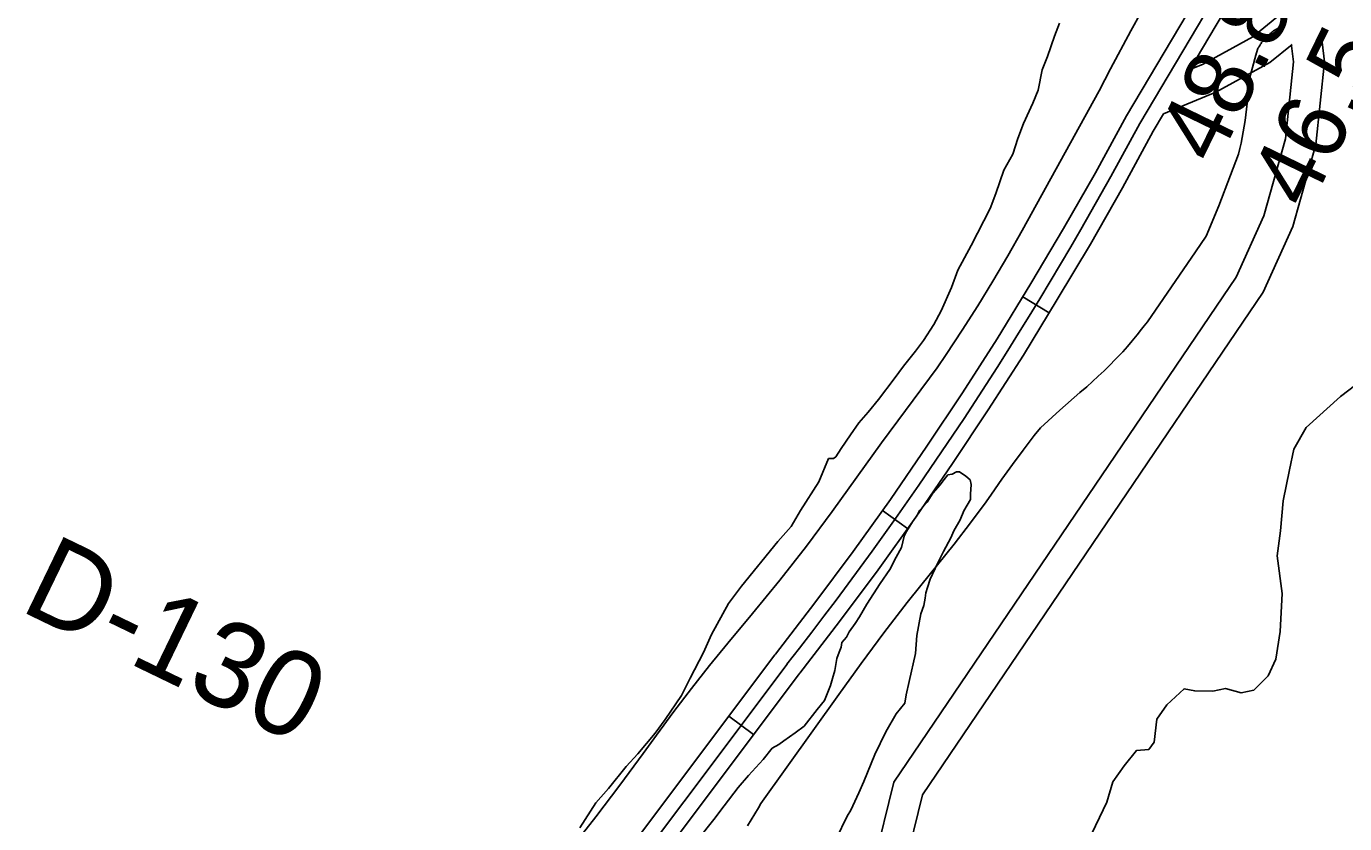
# Model space of a CAD drawing. Extents: x 3180038 to 3217926, y 922069 to 947485.
# Drawn here: x 3187258 to 3188541, y 935984 to 936760 of the extents above; entities that cross this region are included whole.
import ezdxf

# ---------------------------------------------------------------- set-up
doc = ezdxf.new("R2010")
doc.units = 0
for name, color, linetype in [('V-LEVE-TOET', 7, 'Continuous'), ('V-RIVR-EDGE', 7, 'Continuous'), ('V-RIVR-RANG', 7, 'Continuous'), ('V-RIVR-RANG-IDEN', 7, 'Continuous'), ('V-ROAD-CNTR', 7, 'Continuous'), ('V-SITE-VEGE', 7, 'Continuous')]:
    doc.layers.add(name, color=color, linetype=linetype)

msp = doc.modelspace()

# ---------------------------------------------------------------- linework, layer by layer
at = {"layer": 'V-LEVE-TOET'}
for points in [[(3188352.9, 936791.9), (3188332.6, 936755.3), (3188312.8, 936718.4), (3188301.8, 936697.1), (3188301.8, 936697.1), (3188226.8, 936561), (3188226.8, 936561), (3188212.9, 936536.4), (3188198.5, 936512), (3188183.8, 936487.9), (3188168.6, 936464.1), (3188153, 936440.5), (3188144.3, 936427.7), (3188144.3, 936427.7), (3188090.1, 936354.6), (3188042.2, 936287.7), (3188042.2, 936287.7), (3188017, 936254.2), (3187991.1, 936221.1), (3187964.7, 936188.4), (3187940.7, 936159.7), (3187940.7, 936159.7), (3187922.7, 936137.8), (3187905.1, 936115.6), (3187888, 936093.1), (3187871.2, 936070.3), (3187858.3, 936052.3), (3187858.3, 936052.3), (3187835.5, 936021.4), (3187812.2, 935990.8), (3187788.4, 935960.7)], [(3188466.8, 936751.6), (3188467.4, 936752.1), (3188468.1, 936752.7), (3188468.7, 936753.2), (3188469.4, 936753.8), (3188470.1, 936754.3), (3188470.8, 936754.8), (3188471.5, 936755.3), (3188472.1, 936755.8), (3188472.1, 936755.8), (3188473.2, 936756.4), (3188474.2, 936757.1), (3188475.3, 936757.7), (3188476.3, 936758.4), (3188477.3, 936759.1), (3188478.3, 936759.9)], [(3187959.6, 935981.9), (3187963.3, 935987.7), (3187967, 935993.6), (3187970.5, 935999.6), (3187972.8, 936003.6), (3187972.8, 936003.6), (3188048.6, 936109.6), (3188048.6, 936109.6), (3188070.3, 936139.8), (3188092.4, 936169.6), (3188115.1, 936199.1), (3188128.3, 936215.8), (3188128.3, 936215.8), (3188144.7, 936235.8), (3188160.8, 936256), (3188176.6, 936276.6), (3188192, 936297.3), (3188197.2, 936304.6), (3188197.2, 936304.6), (3188207.2, 936319.1), (3188217.4, 936333.5), (3188227.9, 936347.6), (3188238.6, 936361.6), (3188244.7, 936369.2), (3188244.7, 936369.2), (3188263.7, 936386.5), (3188283, 936403.5), (3188289.7, 936409.2), (3188289.7, 936409.2), (3188295.4, 936414.3), (3188301, 936419.4), (3188306.6, 936424.7), (3188312.1, 936430.1), (3188317.5, 936435.5), (3188322.8, 936441), (3188324.7, 936443), (3188324.7, 936443), (3188329.4, 936448.4), (3188334.1, 936453.9), (3188338.7, 936459.5), (3188343.1, 936465.1), (3188345.7, 936468.4), (3188348.9, 936472.2), (3188395.4, 936540.4), (3188405.9, 936555.5), (3188405.9, 936555.5), (3188418.1, 936585.2), (3188429.7, 936615), (3188437.3, 936635.3), (3188437.3, 936635.3), (3188438.6, 936640.8), (3188439.9, 936646.2), (3188441, 936651.7), (3188442, 936657.2), (3188442.9, 936662.7), (3188443.8, 936668.2), (3188444.5, 936673.7), (3188445.2, 936679.3), (3188445.7, 936684.9), (3188446.2, 936690.4), (3188446.5, 936696), (3188446.8, 936701.6), (3188446.9, 936704.3), (3188446.9, 936704.3), (3188454.2, 936731.8), (3188455.8, 936737.3), (3188455.8, 936737.3), (3188456.2, 936738.1), (3188456.6, 936738.8), (3188457.1, 936739.6), (3188457.5, 936740.3), (3188458, 936741.1), (3188458.4, 936741.8), (3188458.9, 936742.5), (3188459.4, 936743.2), (3188459.9, 936743.9), (3188460.4, 936744.6), (3188460.9, 936745.3), (3188461.5, 936746), (3188462, 936746.6), (3188462.6, 936747.3), (3188463.1, 936747.9), (3188463.7, 936748.6), (3188464.3, 936749.2), (3188464.9, 936749.8), (3188465.5, 936750.4), (3188466.1, 936751), (3188466.8, 936751.6)]]:
    msp.add_lwpolyline(points, dxfattribs=at)
at = {"layer": 'V-RIVR-EDGE'}
msp.add_lwpolyline([(3188565.1, 936421.3), (3188536.5, 936399.6), (3188503.3, 936369.6), (3188491.3, 936348.4), (3188487.1, 936328.2), (3188480.8, 936298.1), (3188478.1, 936269.1), (3188474.9, 936244.7), (3188480, 936207.9), (3188477.9, 936171), (3188473.7, 936144.1), (3188466.4, 936128), (3188452.3, 936114.1), (3188439.9, 936111.5), (3188424.8, 936115.7), (3188412.4, 936113.1), (3188394.8, 936113.2), (3188384.4, 936115.3), (3188367.8, 936099.7), (3188357.9, 936085.8), (3188355.2, 936063.5), (3188350, 936056.2), (3188338.1, 936055.2), (3188326.1, 936040.2), (3188315.2, 936024.7), (3188309.4, 936005), (3188291.2, 935967.2)], dxfattribs=at)
at = {"layer": 'V-ROAD-CNTR'}
for p, q in [((3188227.6, 936496.7), (3188253.2, 936481.1)), ((3188091.1, 936288.7), (3188115.5, 936271.2)), ((3187941.6, 936088.7), (3187965.6, 936070.7))]:
    msp.add_line(p, q, dxfattribs=at)
for points in [[(3188389.9, 936717.7), (3188473.2, 936857.9), (3188474.4, 936860.6), (3188478.6, 936870.4), (3188482.7, 936880.4), (3188486.5, 936890.4), (3188490.2, 936900.4), (3188493.8, 936910.6), (3188497.2, 936920.7), (3188500.4, 936931), (3188503.3, 936941.4), (3188506.1, 936951.6), (3188508.8, 936962.1), (3188511.2, 936972.5), (3188513.5, 936983), (3188515.6, 936993.5), (3188517.4, 937003.5), (3188766.5, 938005.7), (3189036.4, 939099.3)], [(3188590.9, 937170.6), (3188515.3, 936861.3), (3188500.1, 936812.2), (3188489.1, 936780.3), (3188451.3, 936749.7), (3188402.2, 936722.8), (3188389.9, 936717.7)], [(3186059.8, 935066.3), (3186493.7, 935122.6), (3186977, 935171.7), (3187080.7, 935213.4), (3187378.1, 935455), (3187701.8, 935784.3), (3187785.7, 935880.7), (3187986.3, 936148.4), (3187986.9, 936149.1), (3188025.3, 936198.9), (3188062.5, 936248.9), (3188099, 936299.6), (3188134.3, 936351.4), (3188168.9, 936403.3), (3188202.7, 936455.8), (3188235.4, 936509.5), (3188267.3, 936563.2), (3188298.3, 936617.3), (3188328.3, 936672.8), (3188446.5, 936871.6)], [(3188341.4, 936665.3), (3188459.8, 936864.8)], [(3188489.1, 936740.7), (3188491, 936725.2), (3188483.1, 936650.4), (3188462.1, 936575.4), (3188435.2, 936515.8), (3188102.2, 936024.6), (3188082.9, 935946.7), (3188076.6, 935849.8), (3188047.1, 935768.7), (3187793, 935454.5), (3187571.4, 935220.4), (3187550.5, 935240.3), (3187496.1, 935257.3), (3187377, 935267.3), (3187331.3, 935217.9)], [(3188518.9, 936744.3), (3188521.2, 936725.4), (3188512.7, 936644.7), (3188490.4, 936565.2), (3188461.5, 936501.1), (3188130, 936012.2), (3188112.7, 935942.1), (3188106.3, 935843.6), (3188073.5, 935753.7), (3187815.6, 935434.7), (3187572.4, 935177.9), (3187534.9, 935213.7), (3187490.3, 935227.7), (3187389.1, 935236.2), (3187344.3, 935187.8)], [(3188489.5, 936742), (3188468, 936724.6), (3188415.2, 936695.7), (3188364.3, 936674.6)], [(3187281.6, 935338), (3187398.3, 935432.8), (3187723.8, 935763.9), (3187809, 935861.8), (3188010, 936130), (3188010.5, 936130.6), (3188049.2, 936180.8), (3188086.7, 936231.1), (3188123.5, 936282.4), (3188159.2, 936334.6), (3188194, 936386.8), (3188228.1, 936439.9), (3188261.1, 936494), (3188293.3, 936548), (3188324.5, 936602.7), (3188354.4, 936657.9), (3188364.3, 936674.6)], [(3184282, 935074.7), (3185479.2, 935059.6), (3186060.6, 935051.3), (3186495.4, 935107.7), (3186980.7, 935157), (3187088.4, 935200.3), (3187388.2, 935443.9), (3187712.8, 935774.1), (3187797.4, 935871.3), (3187998.2, 936139.2)]]:
    msp.add_lwpolyline(points, dxfattribs=at)
msp.add_arc((3185167.6, 938360.5), 3598, 321.8767, 331.8928, dxfattribs=at)
at = {"layer": 'V-SITE-VEGE'}
for p, q in [((3188263.4, 936762.7), (3188258.5, 936750.2)), ((3188258.5, 936750.2), (3188251.5, 936730.5)), ((3188251.5, 936730.5), (3188246.5, 936717.3)), ((3188246.5, 936717.3), (3188242.4, 936697.6)), ((3188242.4, 936697.6), (3188237.4, 936685.1)), ((3188237.4, 936685.1), (3188228.2, 936665.3)), ((3188228.2, 936665.3), (3188222.6, 936650.7)), ((3188222.6, 936650.7), (3188217.7, 936635.3)), ((3188217.7, 936635.3), (3188209.1, 936619.9)), ((3188209.1, 936619.9), (3188201.4, 936597.2)), ((3188201.4, 936597.2), (3188195.7, 936582.6)), ((3188195.7, 936582.6), (3188177.2, 936546.6)), ((3188177.2, 936546.6), (3188164.4, 936522.4)), ((3188164.4, 936522.4), (3188158.1, 936505.6)), ((3188158.1, 936505.6), (3188148.1, 936482.9)), ((3188148.1, 936482.9), (3188141, 936469.6)), ((3188141, 936469.6), (3188131, 936454.2)), ((3188131, 936454.2), (3188123.1, 936443.9)), ((3188123.1, 936443.9), (3188111.6, 936429.2)), ((3188111.6, 936429.2), (3188102.3, 936416.7)), ((3188102.3, 936416.7), (3188087.3, 936396.8)), ((3188087.3, 936396.8), (3188077.2, 936384.3)), ((3188077.2, 936384.3), (3188067.9, 936374)), ((3188067.9, 936374), (3188060, 936362.2)), ((3188060, 936362.2), (3188050.7, 936349)), ((3188050.7, 936349), (3188045.7, 936340.9)), ((3188038.4, 936339.4), (3188029.2, 936316.7)), ((3188043.5, 936339.4), (3188038.4, 936339.4)), ((3188045.7, 936340.9), (3188043.5, 936339.4)), ((3188150.9, 936318.9), (3188147.3, 936313.8)), ((3188154.5, 936323.3), (3188150.9, 936318.9)), ((3188158.9, 936324.1), (3188154.5, 936323.3)), ((3188163.2, 936326.4), (3188158.9, 936324.1)), ((3188166.1, 936326.4), (3188163.2, 936326.4)), ((3188172, 936322.1), (3188166.1, 936326.4)), ((3188176.4, 936318.5), (3188172, 936322.1)), ((3188177.2, 936314.1), (3188176.4, 936318.5)), ((3188029.2, 936316.7), (3188011.4, 936288.8)), ((3188140.1, 936305.7), (3188134.4, 936296.9)), ((3188147.3, 936313.8), (3188140.1, 936305.7)), ((3188176.6, 936304.7), (3188177.2, 936314.1)), ((3188176.7, 936299.6), (3188176.6, 936304.7)), ((3188134.4, 936296.9), (3188127.2, 936288.7)), ((3188170.2, 936288.5), (3188176.7, 936299.6)), ((3188011.4, 936288.8), (3188002.1, 936273.3)), ((3188124.4, 936283.6), (3188120.1, 936277.7)), ((3188127.2, 936288.7), (3188124.4, 936283.6)), ((3188160.3, 936268.8), (3188166.7, 936279.8)), ((3188166.7, 936279.8), (3188170.2, 936288.5)), ((3188002.1, 936273.3), (3187989.1, 936258.6)), ((3188114.4, 936268.2), (3188112.2, 936263.8)), ((3188120.1, 936277.7), (3188114.4, 936268.2)), ((3188157.4, 936262.2), (3188160.3, 936268.8)), ((3187989.1, 936258.6), (3187954, 936215.2)), ((3188112.2, 936263.8), (3188109.5, 936252.8)), ((3188150.3, 936248.9), (3188157.4, 936262.2)), ((3188104.5, 936243.3), (3188098.1, 936231.5)), ((3188109.5, 936252.8), (3188104.5, 936243.3)), ((3188144.6, 936237.2), (3188150.3, 936248.9)), ((3188098.1, 936231.5), (3188088.8, 936217.6)), ((3188137.5, 936221.8), (3188144.6, 936237.2)), ((3187954, 936215.2), (3187941.1, 936198.2)), ((3188088.8, 936217.6), (3188075.9, 936197.7)), ((3188134.7, 936213.8), (3188137.5, 936221.8)), ((3188131.3, 936196.2), (3188132.7, 936203.5)), ((3188132.7, 936203.5), (3188133.3, 936208.7)), ((3188133.3, 936208.7), (3188134.7, 936213.8)), ((3187941.1, 936198.2), (3187924.7, 936168.2)), ((3188075.9, 936197.7), (3188068.8, 936185.3)), ((3188128.5, 936188.2), (3188131.3, 936196.2)), ((3188064.5, 936178.7), (3188058.7, 936170.6)), ((3188068.8, 936185.3), (3188064.5, 936178.7)), ((3188124.4, 936167), (3188128.5, 936188.2)), ((3187924.7, 936168.2), (3187916.9, 936150.6)), ((3188055.9, 936165.4), (3188051.6, 936160.3)), ((3188058.7, 936170.6), (3188055.9, 936165.4)), ((3188123.1, 936149.5), (3188124.4, 936167)), ((3187916.9, 936150.6), (3187904.1, 936125.6)), ((3188048.8, 936150.8), (3188046.7, 936144.9)), ((3188050.9, 936155.9), (3188048.8, 936150.8)), ((3188051.6, 936160.3), (3188050.9, 936155.9)), ((3188046.7, 936144.9), (3188044.6, 936133.2)), ((3188116.9, 936122.5), (3188123.1, 936149.5)), ((3187904.1, 936125.6), (3187895.5, 936108.8)), ((3188042.5, 936125.2), (3188040.4, 936118.6)), ((3188044.6, 936133.2), (3188042.5, 936125.2)), ((3188040.4, 936118.6), (3188034.8, 936103.9)), ((3188114.2, 936109.3), (3188116.9, 936122.5)), ((3187895.5, 936108.8), (3187879.8, 936085.3)), ((3188034.8, 936103.9), (3188027.6, 936095.1)), ((3188104.2, 936091), (3188112.8, 936101.3)), ((3188112.8, 936101.3), (3188114.2, 936109.3)), ((3188027.6, 936095.1), (3188014.7, 936078.9)), ((3188094.2, 936073.3), (3188104.2, 936091)), ((3187879.8, 936085.3), (3187869.8, 936072)), ((3188014.7, 936078.9), (3188006, 936072.3)), ((3187869.8, 936072), (3187853.2, 936052.1)), ((3187990.1, 936061.1), (3187983.6, 936057.4)), ((3187995.2, 936064.8), (3187990.1, 936061.1)), ((3188006, 936072.3), (3187995.2, 936064.8)), ((3188083.5, 936051.4), (3188094.2, 936073.3)), ((3187853.2, 936052.1), (3187841.7, 936039.6)), ((3187983.6, 936057.4), (3187975, 936046.4)), ((3188072.9, 936025), (3188083.5, 936051.4)), ((3187841.7, 936039.6), (3187824.5, 936018.2)), ((3187975, 936046.4), (3187960.6, 936030.9)), ((3187960.6, 936030.9), (3187950.6, 936019.1)), ((3188068, 936014), (3188072.9, 936025)), ((3187824.5, 936018.2), (3187812.3, 936004.3)), ((3187950.6, 936019.1), (3187937, 936001.4)), ((3188060.2, 935997.1), (3188068, 936014)), ((3187812.3, 936004.3), (3187796.6, 935980)), ((3187937, 936001.4), (3187926.9, 935988.2)), ((3188056.6, 935991.3), (3188060.2, 935997.1)), ((3187926.9, 935988.2), (3187911.9, 935969.1)), ((3188045.9, 935969.3), (3188056.6, 935991.3))]:
    msp.add_line(p, q, dxfattribs=at)

# ---------------------------------------------------------------- texts
at = {"layer": 'V-RIVR-RANG'}
for s, p in [('48.8', (3188415.8, 936623.1)), ('46.5', (3188505.9, 936579.6))]:
    msp.add_text(s, height=67, rotation=64.0783, dxfattribs=at).set_placement(p)
at = {"layer": 'V-RIVR-RANG-IDEN'}
msp.add_text('D-130', height=83, rotation=334.2152, dxfattribs=at).set_placement((3187250.1, 936192.2))

doc.saveas('drawing.dxf')
